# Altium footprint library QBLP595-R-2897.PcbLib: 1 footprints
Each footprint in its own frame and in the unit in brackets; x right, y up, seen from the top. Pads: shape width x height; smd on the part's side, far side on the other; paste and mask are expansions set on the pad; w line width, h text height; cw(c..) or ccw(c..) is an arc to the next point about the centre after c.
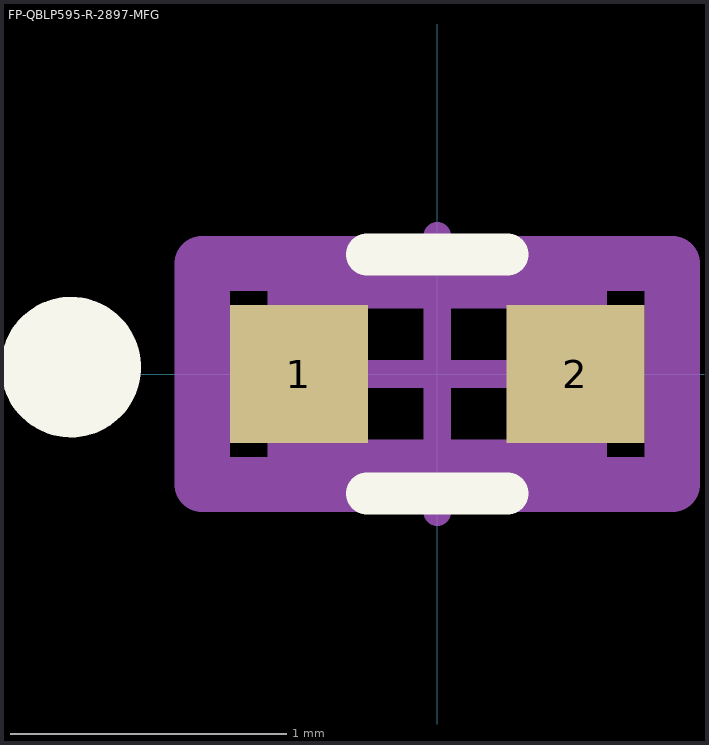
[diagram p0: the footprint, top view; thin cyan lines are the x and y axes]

## FP-QBLP595-R-2897-MFG [mm]
pads (2):
  rect 0.5x0.5 smd paste+0 mask+0: 1(-0.5,0) 2(0.5,0)
Top Overlay:
  circle w0.254: c-1.325,0.025 r0.127
  lines w0.152: -0.254,-0.432 0.254,-0.432 ; -0.254,0.432 0.254,0.432
Mechanical 5:
  lines w0.2: -0.85,-0.4 0.85,-0.4 0.85,0.4 -0.85,0.4 -0.85,-0.4
  text ".Designator" at 0,0 h1
Mechanical 13:
  lines w0.127: -0.55,-0.3 0.55,-0.3 0.55,0.3 -0.55,0.3 -0.55,-0.3
Mechanical 15:
  lines w0.2: -0.85,-0.4 0.85,-0.4 0.85,0.4 -0.85,0.4 -0.85,-0.4
Mechanical 16:
  lines w0.1: -0.5,0 0.5,0 ; 0,-0.5 0,0.5
3D body "QBLP595.step": height 0.5, standoff 0, extent -0.521,-0.25 0.479,0.25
